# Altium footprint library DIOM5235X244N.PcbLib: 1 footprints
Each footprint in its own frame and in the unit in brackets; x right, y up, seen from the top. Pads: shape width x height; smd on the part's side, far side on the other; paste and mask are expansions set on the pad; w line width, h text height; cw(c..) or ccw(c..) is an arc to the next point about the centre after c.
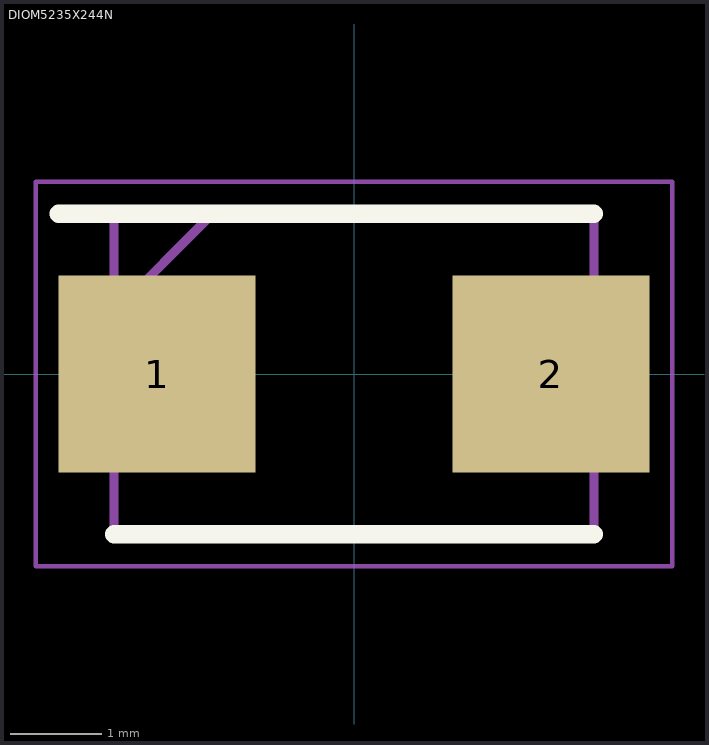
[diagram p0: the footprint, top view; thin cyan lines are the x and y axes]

## DIOM5235X244N [mm]
pads (2):
  rect 2.15x2.15 smd: 1(-2.15,0) 2(2.15,0)
Top Overlay:
  lines w0.2: -3.225,1.75 2.62,1.75 ; -2.62,-1.75 2.62,-1.75
Mechanical 15:
  lines w0.1: -2.62,0.675 -1.545,1.75 ; -2.62,-1.75 2.62,-1.75 2.62,1.75 -2.62,1.75 -2.62,-1.75
Mechanical 20:
  lines w0.05: -3.475,-2.1 3.475,-2.1 3.475,2.1 -3.475,2.1 -3.475,-2.1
